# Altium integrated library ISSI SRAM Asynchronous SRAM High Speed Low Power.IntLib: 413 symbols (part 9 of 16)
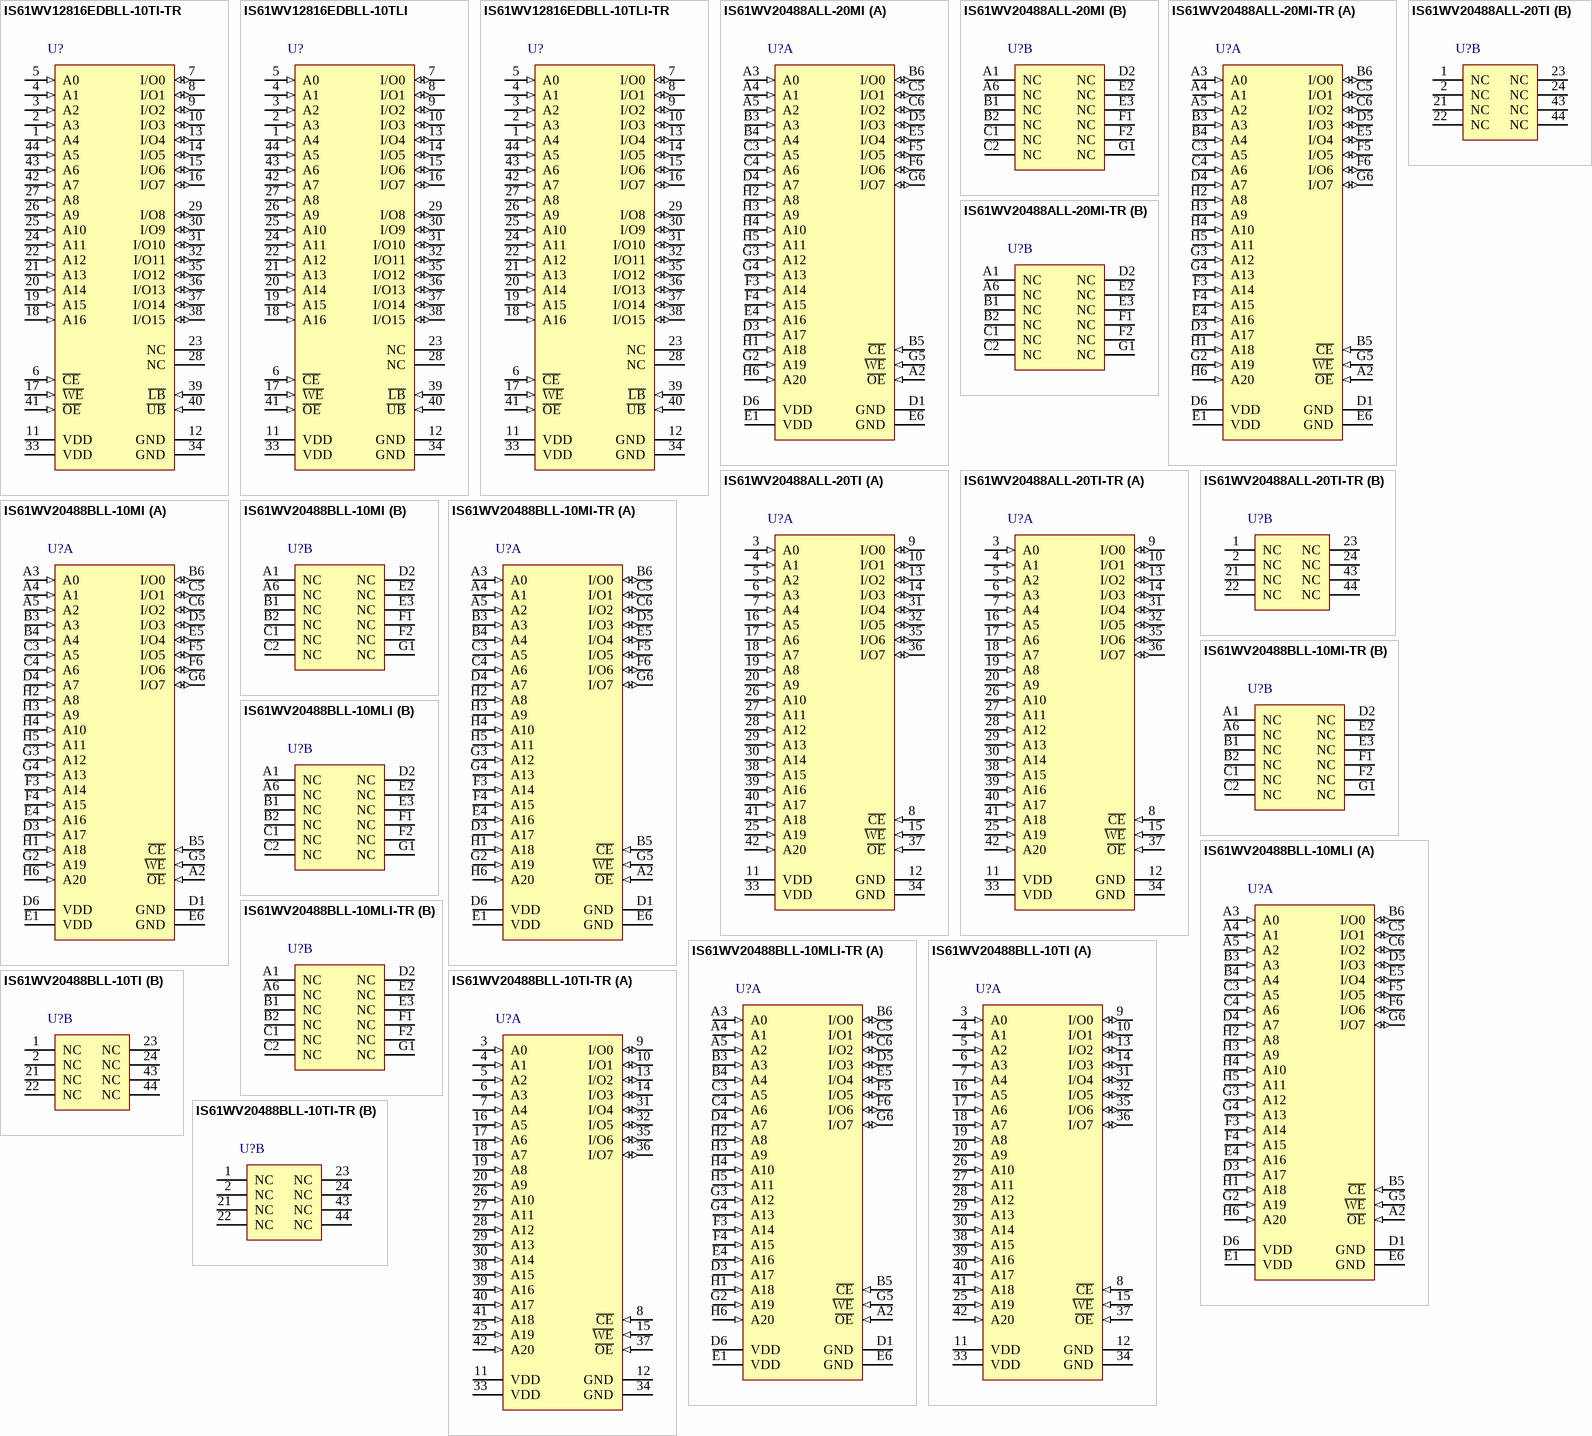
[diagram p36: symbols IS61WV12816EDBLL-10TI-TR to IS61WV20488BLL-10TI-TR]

## IS61WV20488BLL-10MI
designator U?
16 M High Speed CMOS SRAM, 2 M x 8, -40 to 85 degC, 48-Pin BGA (TF-BGA-48); Manufacturer: Integrated Silicon Solution Inc (ISSI); PartNumber: IS61WV20488BLL-10MI; Organization: 2M x 8; Packing: Tray / Tube; Speed (ns): 10
footprint ISSI-TF-BGA-48-9000x11000DE (BGA, 48-Balls, Body 11x9mm, Pitch 0.75mm)
part A pins: A2 ~{OE} (in) "Output Enable Input", A3 A0 (in) "Address Input", A4 A1 (in) "Address Input", A5 A2 (in) "Address Input", B3 A3 (in) "Address Input", B4 A4 (in) "Address Input", B5 ~{CE} (in) "Chip Enable Input", B6 I/O0 (io) "Data Input / Output", C3 A5 (in) "Address Input", C4 A6 (in) "Address Input", C5 I/O1 (io) "Data Input / Output", C6 I/O2 (io) "Data Input / Output", D1 GND (power) "Ground", D3 A17 (in) "Address Input", D4 A7 (in) "Address Input", D5 I/O3 (io) "Data Input / Output", D6 VDD (power) "Power", E1 VDD (power) "Power", E4 A16 (in) "Address Input", E5 I/O4 (io) "Data Input / Output", E6 GND (power) "Ground", F3 A14 (in) "Address Input", F4 A15 (in) "Address Input", F5 I/O5 (io) "Data Input / Output", F6 I/O6 (io) "Data Input / Output", G2 A19 (in) "Address Input", G3 A12 (in) "Address Input", G4 A13 (in) "Address Input", G5 ~{WE} (in) "Write Enable Input", G6 I/O7 (io) "Data Input / Output", H1 A18 (in) "Address Input", H2 A8 (in) "Address Input", H3 A9 (in) "Address Input", H4 A10 (in) "Address Input", H5 A11 (in) "Address Input", H6 A20 (in) "Address Input"
part B pins: A1 NC "No Connection", A6 NC "No Connection", B1 NC "No Connection", B2 NC "No Connection", C1 NC "No Connection", C2 NC "No Connection", D2 NC "No Connection", E2 NC "No Connection", E3 NC "No Connection", F1 NC "No Connection", F2 NC "No Connection", G1 NC "No Connection"

## IS61WV20488BLL-10MI-TR
designator U?
16 M High Speed CMOS SRAM, 2 M x 8, -40 to 85 degC, 48-Pin BGA (TF-BGA-48); Manufacturer: Integrated Silicon Solution Inc (ISSI); PartNumber: IS61WV20488BLL-10MI-TR; Organization: 2M x 8; Packing: Tape & Reel; Speed (ns): 10
footprint ISSI-TF-BGA-48-9000x11000DE (BGA, 48-Balls, Body 11x9mm, Pitch 0.75mm)
part A pins: A2 ~{OE} (in) "Output Enable Input", A3 A0 (in) "Address Input", A4 A1 (in) "Address Input", A5 A2 (in) "Address Input", B3 A3 (in) "Address Input", B4 A4 (in) "Address Input", B5 ~{CE} (in) "Chip Enable Input", B6 I/O0 (io) "Data Input / Output", C3 A5 (in) "Address Input", C4 A6 (in) "Address Input", C5 I/O1 (io) "Data Input / Output", C6 I/O2 (io) "Data Input / Output", D1 GND (power) "Ground", D3 A17 (in) "Address Input", D4 A7 (in) "Address Input", D5 I/O3 (io) "Data Input / Output", D6 VDD (power) "Power", E1 VDD (power) "Power", E4 A16 (in) "Address Input", E5 I/O4 (io) "Data Input / Output", E6 GND (power) "Ground", F3 A14 (in) "Address Input", F4 A15 (in) "Address Input", F5 I/O5 (io) "Data Input / Output", F6 I/O6 (io) "Data Input / Output", G2 A19 (in) "Address Input", G3 A12 (in) "Address Input", G4 A13 (in) "Address Input", G5 ~{WE} (in) "Write Enable Input", G6 I/O7 (io) "Data Input / Output", H1 A18 (in) "Address Input", H2 A8 (in) "Address Input", H3 A9 (in) "Address Input", H4 A10 (in) "Address Input", H5 A11 (in) "Address Input", H6 A20 (in) "Address Input"
part B pins: A1 NC "No Connection", A6 NC "No Connection", B1 NC "No Connection", B2 NC "No Connection", C1 NC "No Connection", C2 NC "No Connection", D2 NC "No Connection", E2 NC "No Connection", E3 NC "No Connection", F1 NC "No Connection", F2 NC "No Connection", G1 NC "No Connection"

## IS61WV20488BLL-10MLI
designator U?
16 M High Speed CMOS SRAM, 2 M x 8, -40 to 85 degC, 48-Pin BGA (TF-BGA-48), Pb-Free; Manufacturer: Integrated Silicon Solution Inc (ISSI); PartNumber: IS61WV20488BLL-10MLI; Organization: 2M x 8; Packing: Tray / Tube; Speed (ns): 10
footprint ISSI-TF-BGA-48-9000x11000DE (BGA, 48-Balls, Body 11x9mm, Pitch 0.75mm)
part A pins: A2 ~{OE} (in) "Output Enable Input", A3 A0 (in) "Address Input", A4 A1 (in) "Address Input", A5 A2 (in) "Address Input", B3 A3 (in) "Address Input", B4 A4 (in) "Address Input", B5 ~{CE} (in) "Chip Enable Input", B6 I/O0 (io) "Data Input / Output", C3 A5 (in) "Address Input", C4 A6 (in) "Address Input", C5 I/O1 (io) "Data Input / Output", C6 I/O2 (io) "Data Input / Output", D1 GND (power) "Ground", D3 A17 (in) "Address Input", D4 A7 (in) "Address Input", D5 I/O3 (io) "Data Input / Output", D6 VDD (power) "Power", E1 VDD (power) "Power", E4 A16 (in) "Address Input", E5 I/O4 (io) "Data Input / Output", E6 GND (power) "Ground", F3 A14 (in) "Address Input", F4 A15 (in) "Address Input", F5 I/O5 (io) "Data Input / Output", F6 I/O6 (io) "Data Input / Output", G2 A19 (in) "Address Input", G3 A12 (in) "Address Input", G4 A13 (in) "Address Input", G5 ~{WE} (in) "Write Enable Input", G6 I/O7 (io) "Data Input / Output", H1 A18 (in) "Address Input", H2 A8 (in) "Address Input", H3 A9 (in) "Address Input", H4 A10 (in) "Address Input", H5 A11 (in) "Address Input", H6 A20 (in) "Address Input"
part B pins: A1 NC "No Connection", A6 NC "No Connection", B1 NC "No Connection", B2 NC "No Connection", C1 NC "No Connection", C2 NC "No Connection", D2 NC "No Connection", E2 NC "No Connection", E3 NC "No Connection", F1 NC "No Connection", F2 NC "No Connection", G1 NC "No Connection"

## IS61WV20488BLL-10MLI-TR
designator U?
16 M High Speed CMOS SRAM, 2 M x 8, -40 to 85 degC, 48-Pin BGA (TF-BGA-48), Pb-Free; Manufacturer: Integrated Silicon Solution Inc (ISSI); PartNumber: IS61WV20488BLL-10MLI-TR; Organization: 2M x 8; Packing: Tape & Reel; Speed (ns): 10
footprint ISSI-TF-BGA-48-9000x11000DE (BGA, 48-Balls, Body 11x9mm, Pitch 0.75mm)
part A pins: A2 ~{OE} (in) "Output Enable Input", A3 A0 (in) "Address Input", A4 A1 (in) "Address Input", A5 A2 (in) "Address Input", B3 A3 (in) "Address Input", B4 A4 (in) "Address Input", B5 ~{CE} (in) "Chip Enable Input", B6 I/O0 (io) "Data Input / Output", C3 A5 (in) "Address Input", C4 A6 (in) "Address Input", C5 I/O1 (io) "Data Input / Output", C6 I/O2 (io) "Data Input / Output", D1 GND (power) "Ground", D3 A17 (in) "Address Input", D4 A7 (in) "Address Input", D5 I/O3 (io) "Data Input / Output", D6 VDD (power) "Power", E1 VDD (power) "Power", E4 A16 (in) "Address Input", E5 I/O4 (io) "Data Input / Output", E6 GND (power) "Ground", F3 A14 (in) "Address Input", F4 A15 (in) "Address Input", F5 I/O5 (io) "Data Input / Output", F6 I/O6 (io) "Data Input / Output", G2 A19 (in) "Address Input", G3 A12 (in) "Address Input", G4 A13 (in) "Address Input", G5 ~{WE} (in) "Write Enable Input", G6 I/O7 (io) "Data Input / Output", H1 A18 (in) "Address Input", H2 A8 (in) "Address Input", H3 A9 (in) "Address Input", H4 A10 (in) "Address Input", H5 A11 (in) "Address Input", H6 A20 (in) "Address Input"
part B pins: A1 NC "No Connection", A6 NC "No Connection", B1 NC "No Connection", B2 NC "No Connection", C1 NC "No Connection", C2 NC "No Connection", D2 NC "No Connection", E2 NC "No Connection", E3 NC "No Connection", F1 NC "No Connection", F2 NC "No Connection", G1 NC "No Connection"

## IS61WV20488BLL-10TI
designator U?
16 M High Speed CMOS SRAM, 2 M x 8, -40 to 85 degC, 44-Pin SOP (TSOP-2-44); Manufacturer: Integrated Silicon Solution Inc (ISSI); PartNumber: IS61WV20488BLL-10TI; Organization: 2M x 8; Packing: Tray / Tube; Speed (ns): 10
footprint ISSI-TSOP-2-44_N (SOP, 44-Leads, Body 18.5x10.3mm, Pitch 0.8mm, IPC Medium Density)
part A pins: 3 A0 (in) "Address Inputs", 4 A1 (in) "Address Inputs", 5 A2 (in) "Address Inputs", 6 A3 (in) "Address Inputs", 7 A4 (in) "Address Inputs", 8 ~{CE} (in) "Chip Enable Input", 9 I/O0 (io) "Data Input / Output", 10 I/O1 (io) "Data Input / Output", 11 VDD (power) "Power", 12 GND (power) "Ground", 13 I/O2 (io) "Data Input / Output", 14 I/O3 (io) "Data Input / Output", 15 ~{WE} (in) "Write Enable Input", 16 A5 (in) "Address Inputs", 17 A6 (in) "Address Inputs", 18 A7 (in) "Address Inputs", 19 A8 (in) "Address Inputs", 20 A9 (in) "Address Inputs", 25 A19 (in) "Address Inputs", 26 A10 (in) "Address Inputs", 27 A11 (in) "Address Inputs", 28 A12 (in) "Address Inputs", 29 A13 (in) "Address Inputs", 30 A14 (in) "Address Inputs", 31 I/O4 (io) "Data Input / Output", 32 I/O5 (io) "Data Input / Output", 33 VDD (power) "Power", 34 GND (power) "Ground", 35 I/O6 (io) "Data Input / Output", 36 I/O7 (io) "Data Input / Output", 37 ~{OE} (in) "Output Enable Input", 38 A15 (in) "Address Inputs", 39 A16 (in) "Address Inputs", 40 A17 (in) "Address Inputs", 41 A18 (in) "Address Inputs", 42 A20 (in) "Address Inputs"
part B pins: 1 NC "No Connection", 2 NC "No Connection", 21 NC "No Connection", 22 NC "No Connection", 23 NC "No Connection", 24 NC "No Connection", 43 NC "No Connection", 44 NC "No Connection"

## IS61WV20488BLL-10TI-TR
designator U?
16 M High Speed CMOS SRAM, 2 M x 8, -40 to 85 degC, 44-Pin SOP (TSOP-2-44); Manufacturer: Integrated Silicon Solution Inc (ISSI); PartNumber: IS61WV20488BLL-10TI-TR; Organization: 2M x 8; Packing: Tape & Reel; Speed (ns): 10
footprint ISSI-TSOP-2-44_N (SOP, 44-Leads, Body 18.5x10.3mm, Pitch 0.8mm, IPC Medium Density)
part A pins: 3 A0 (in) "Address Inputs", 4 A1 (in) "Address Inputs", 5 A2 (in) "Address Inputs", 6 A3 (in) "Address Inputs", 7 A4 (in) "Address Inputs", 8 ~{CE} (in) "Chip Enable Input", 9 I/O0 (io) "Data Input / Output", 10 I/O1 (io) "Data Input / Output", 11 VDD (power) "Power", 12 GND (power) "Ground", 13 I/O2 (io) "Data Input / Output", 14 I/O3 (io) "Data Input / Output", 15 ~{WE} (in) "Write Enable Input", 16 A5 (in) "Address Inputs", 17 A6 (in) "Address Inputs", 18 A7 (in) "Address Inputs", 19 A8 (in) "Address Inputs", 20 A9 (in) "Address Inputs", 25 A19 (in) "Address Inputs", 26 A10 (in) "Address Inputs", 27 A11 (in) "Address Inputs", 28 A12 (in) "Address Inputs", 29 A13 (in) "Address Inputs", 30 A14 (in) "Address Inputs", 31 I/O4 (io) "Data Input / Output", 32 I/O5 (io) "Data Input / Output", 33 VDD (power) "Power", 34 GND (power) "Ground", 35 I/O6 (io) "Data Input / Output", 36 I/O7 (io) "Data Input / Output", 37 ~{OE} (in) "Output Enable Input", 38 A15 (in) "Address Inputs", 39 A16 (in) "Address Inputs", 40 A17 (in) "Address Inputs", 41 A18 (in) "Address Inputs", 42 A20 (in) "Address Inputs"
part B pins: 1 NC "No Connection", 2 NC "No Connection", 21 NC "No Connection", 22 NC "No Connection", 23 NC "No Connection", 24 NC "No Connection", 43 NC "No Connection", 44 NC "No Connection"

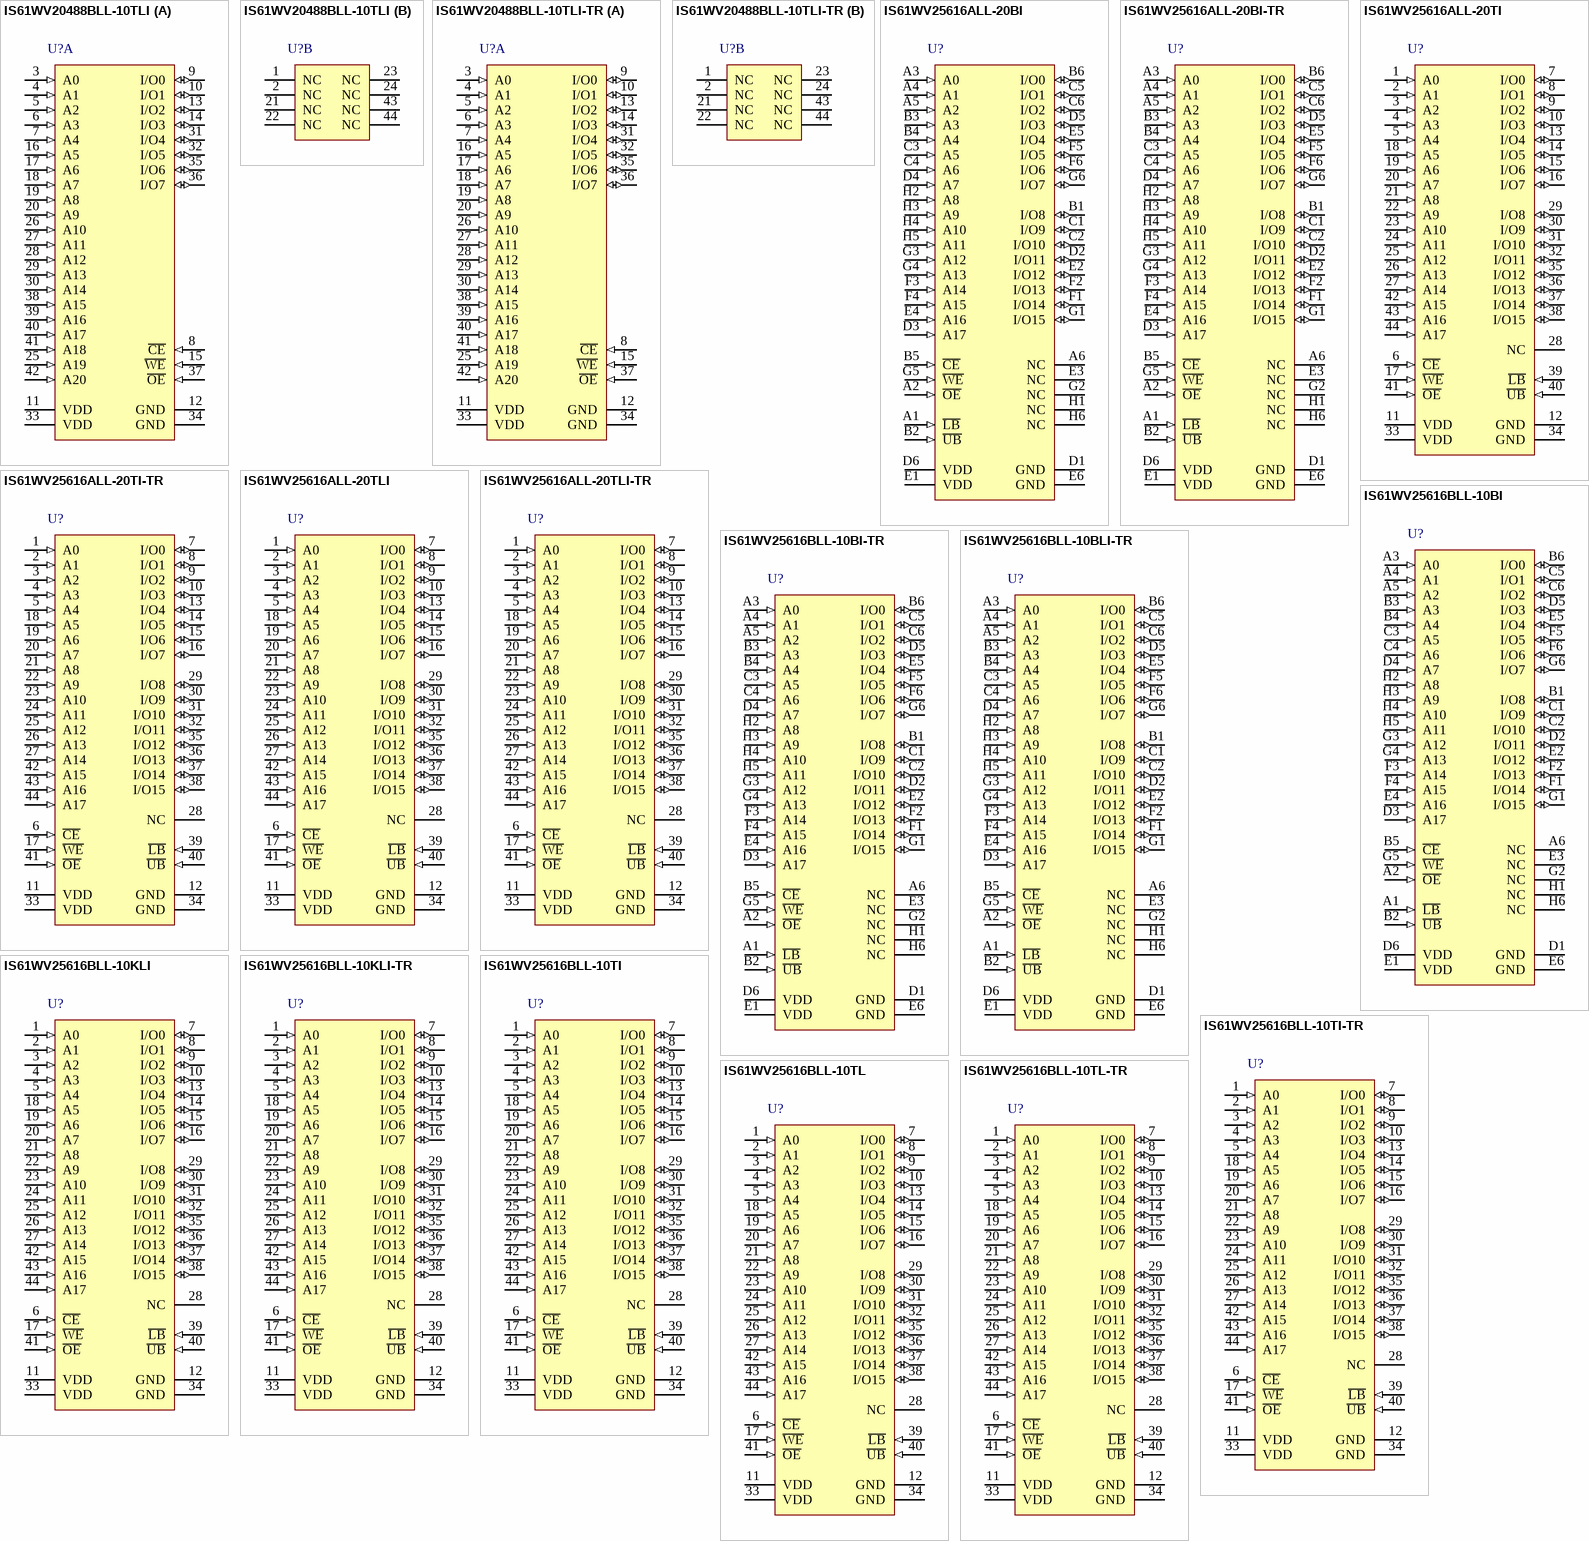
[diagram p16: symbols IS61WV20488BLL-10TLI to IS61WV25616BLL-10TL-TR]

## IS61WV20488BLL-10TLI
designator U?
16 M High Speed CMOS SRAM, 2 M x 8, -40 to 85 degC, 44-Pin SOP (TSOP-2-44), Pb-Free; Manufacturer: Integrated Silicon Solution Inc (ISSI); PartNumber: IS61WV20488BLL-10TLI; Organization: 2M x 8; Packing: Tray / Tube; Speed (ns): 10
footprint ISSI-TSOP-2-44_N (SOP, 44-Leads, Body 18.5x10.3mm, Pitch 0.8mm, IPC Medium Density)
part A pins: 3 A0 (in) "Address Inputs", 4 A1 (in) "Address Inputs", 5 A2 (in) "Address Inputs", 6 A3 (in) "Address Inputs", 7 A4 (in) "Address Inputs", 8 ~{CE} (in) "Chip Enable Input", 9 I/O0 (io) "Data Input / Output", 10 I/O1 (io) "Data Input / Output", 11 VDD (power) "Power", 12 GND (power) "Ground", 13 I/O2 (io) "Data Input / Output", 14 I/O3 (io) "Data Input / Output", 15 ~{WE} (in) "Write Enable Input", 16 A5 (in) "Address Inputs", 17 A6 (in) "Address Inputs", 18 A7 (in) "Address Inputs", 19 A8 (in) "Address Inputs", 20 A9 (in) "Address Inputs", 25 A19 (in) "Address Inputs", 26 A10 (in) "Address Inputs", 27 A11 (in) "Address Inputs", 28 A12 (in) "Address Inputs", 29 A13 (in) "Address Inputs", 30 A14 (in) "Address Inputs", 31 I/O4 (io) "Data Input / Output", 32 I/O5 (io) "Data Input / Output", 33 VDD (power) "Power", 34 GND (power) "Ground", 35 I/O6 (io) "Data Input / Output", 36 I/O7 (io) "Data Input / Output", 37 ~{OE} (in) "Output Enable Input", 38 A15 (in) "Address Inputs", 39 A16 (in) "Address Inputs", 40 A17 (in) "Address Inputs", 41 A18 (in) "Address Inputs", 42 A20 (in) "Address Inputs"
part B pins: 1 NC "No Connection", 2 NC "No Connection", 21 NC "No Connection", 22 NC "No Connection", 23 NC "No Connection", 24 NC "No Connection", 43 NC "No Connection", 44 NC "No Connection"

## IS61WV20488BLL-10TLI-TR
designator U?
16 M High Speed CMOS SRAM, 2 M x 8, -40 to 85 degC, 44-Pin SOP (TSOP-2-44), Pb-Free; Manufacturer: Integrated Silicon Solution Inc (ISSI); PartNumber: IS61WV20488BLL-10TLI-TR; Organization: 2M x 8; Packing: Tape & Reel; Speed (ns): 10
footprint ISSI-TSOP-2-44_N (SOP, 44-Leads, Body 18.5x10.3mm, Pitch 0.8mm, IPC Medium Density)
part A pins: 3 A0 (in) "Address Inputs", 4 A1 (in) "Address Inputs", 5 A2 (in) "Address Inputs", 6 A3 (in) "Address Inputs", 7 A4 (in) "Address Inputs", 8 ~{CE} (in) "Chip Enable Input", 9 I/O0 (io) "Data Input / Output", 10 I/O1 (io) "Data Input / Output", 11 VDD (power) "Power", 12 GND (power) "Ground", 13 I/O2 (io) "Data Input / Output", 14 I/O3 (io) "Data Input / Output", 15 ~{WE} (in) "Write Enable Input", 16 A5 (in) "Address Inputs", 17 A6 (in) "Address Inputs", 18 A7 (in) "Address Inputs", 19 A8 (in) "Address Inputs", 20 A9 (in) "Address Inputs", 25 A19 (in) "Address Inputs", 26 A10 (in) "Address Inputs", 27 A11 (in) "Address Inputs", 28 A12 (in) "Address Inputs", 29 A13 (in) "Address Inputs", 30 A14 (in) "Address Inputs", 31 I/O4 (io) "Data Input / Output", 32 I/O5 (io) "Data Input / Output", 33 VDD (power) "Power", 34 GND (power) "Ground", 35 I/O6 (io) "Data Input / Output", 36 I/O7 (io) "Data Input / Output", 37 ~{OE} (in) "Output Enable Input", 38 A15 (in) "Address Inputs", 39 A16 (in) "Address Inputs", 40 A17 (in) "Address Inputs", 41 A18 (in) "Address Inputs", 42 A20 (in) "Address Inputs"
part B pins: 1 NC "No Connection", 2 NC "No Connection", 21 NC "No Connection", 22 NC "No Connection", 23 NC "No Connection", 24 NC "No Connection", 43 NC "No Connection", 44 NC "No Connection"

## IS61WV25616ALL-20BI
designator U?
4 M High Speed Asynchronous CMOS SRAM, 256 K x 16, -40 to 85 degC, 48-Pin BGA (TF-BGA-48); Manufacturer: Integrated Silicon Solution Inc (ISSI); PartNumber: IS61WV25616ALL-20BI; Packing: Tray / Tube; Speed (ns): 20
footprint ISSI-TF-BGA-48-6000X8000DE (BGA, 48-Balls, Body 8x6mm, Pitch 0.75mm)
pins: A1 ~{LB} (in) "Lower-byte Control (I/O0-I/O7)", A2 ~{OE} (in) "Output Enable Input", A3 A0 (in) "Address Input", A4 A1 (in) "Address Input", A5 A2 (in) "Address Input", A6 NC "No Connection", B1 I/O8 (io) "Data Input/Output", B2 ~{UB} (in) "Upper-byte Control (I/O8-I/O15)", B3 A3 (in) "Address Input", B4 A4 (in) "Address Input", B5 ~{CE} (in) "Chip Enable Input", B6 I/O0 (io) "Data Input/Output", C1 I/O9 (io) "Data Input/Output", C2 I/O10 (io) "Data Input/Output", C3 A5 (in) "Address Input", C4 A6 (in) "Address Input", C5 I/O1 (io) "Data Input/Output", C6 I/O2 (io) "Data Input/Output", D1 GND (power) "Ground", D2 I/O11 (io) "Data Input/Output", D3 A17 (in) "Address Input", D4 A7 (in) "Address Input", D5 I/O3 (io) "Data Input/Output", D6 VDD (power) "Power", E1 VDD (power) "Power", E2 I/O12 (io) "Data Input/Output", E3 NC "No Connection", E4 A16 (in) "Address Input", E5 I/O4 (io) "Data Input/Output", E6 GND (power) "Ground", F1 I/O14 (io) "Data Input/Output", F2 I/O13 (io) "Data Input/Output", F3 A14 (in) "Address Input", F4 A15 (in) "Address Input", F5 I/O5 (io) "Data Input/Output", F6 I/O6 (io) "Data Input/Output", G1 I/O15 (io) "Data Input/Output", G2 NC "No Connection", G3 A12 (in) "Address Input", G4 A13 (in) "Address Input", G5 ~{WE} (in) "Write Enable Input", G6 I/O7 (io) "Data Input/Output", H1 NC "No Connection", H2 A8 (in) "Address Input", H3 A9 (in) "Address Input", H4 A10 (in) "Address Input", H5 A11 (in) "Address Input", H6 NC "No Connection"

## IS61WV25616ALL-20BI-TR
designator U?
4 M High Speed Asynchronous CMOS SRAM, 256 K x 16, -40 to 85 degC, 48-Pin BGA (TF-BGA-48); Manufacturer: Integrated Silicon Solution Inc (ISSI); PartNumber: IS61WV25616ALL-20BI-TR; Packing: Tape & Reel; Speed (ns): 20
footprint ISSI-TF-BGA-48-6000X8000DE (BGA, 48-Balls, Body 8x6mm, Pitch 0.75mm)
pins: A1 ~{LB} (in) "Lower-byte Control (I/O0-I/O7)", A2 ~{OE} (in) "Output Enable Input", A3 A0 (in) "Address Input", A4 A1 (in) "Address Input", A5 A2 (in) "Address Input", A6 NC "No Connection", B1 I/O8 (io) "Data Input/Output", B2 ~{UB} (in) "Upper-byte Control (I/O8-I/O15)", B3 A3 (in) "Address Input", B4 A4 (in) "Address Input", B5 ~{CE} (in) "Chip Enable Input", B6 I/O0 (io) "Data Input/Output", C1 I/O9 (io) "Data Input/Output", C2 I/O10 (io) "Data Input/Output", C3 A5 (in) "Address Input", C4 A6 (in) "Address Input", C5 I/O1 (io) "Data Input/Output", C6 I/O2 (io) "Data Input/Output", D1 GND (power) "Ground", D2 I/O11 (io) "Data Input/Output", D3 A17 (in) "Address Input", D4 A7 (in) "Address Input", D5 I/O3 (io) "Data Input/Output", D6 VDD (power) "Power", E1 VDD (power) "Power", E2 I/O12 (io) "Data Input/Output", E3 NC "No Connection", E4 A16 (in) "Address Input", E5 I/O4 (io) "Data Input/Output", E6 GND (power) "Ground", F1 I/O14 (io) "Data Input/Output", F2 I/O13 (io) "Data Input/Output", F3 A14 (in) "Address Input", F4 A15 (in) "Address Input", F5 I/O5 (io) "Data Input/Output", F6 I/O6 (io) "Data Input/Output", G1 I/O15 (io) "Data Input/Output", G2 NC "No Connection", G3 A12 (in) "Address Input", G4 A13 (in) "Address Input", G5 ~{WE} (in) "Write Enable Input", G6 I/O7 (io) "Data Input/Output", H1 NC "No Connection", H2 A8 (in) "Address Input", H3 A9 (in) "Address Input", H4 A10 (in) "Address Input", H5 A11 (in) "Address Input", H6 NC "No Connection"

## IS61WV25616ALL-20TI
designator U?
4 M High Speed Asynchronous CMOS SRAM, 256 K x 16, -40 to 85 degC, 44-Pin SOP (TSOP-2-44); Manufacturer: Integrated Silicon Solution Inc (ISSI); PartNumber: IS61WV25616ALL-20TI; Packing: Tray / Tube; Speed (ns): 20
footprint ISSI-TSOP-2-44_N (SOP, 44-Leads, Body 18.5x10.3mm, Pitch 0.8mm, IPC Medium Density)
pins: 1 A0 (in) "Address Input", 2 A1 (in) "Address Input", 3 A2 (in) "Address Input", 4 A3 (in) "Address Input", 5 A4 (in) "Address Input", 6 ~{CE} (in) "Chip Enable Input", 7 I/O0 (io) "Data Input/Output", 8 I/O1 (io) "Data Input/Output", 9 I/O2 (io) "Data Input/Output", 10 I/O3 (io) "Data Input/Output", 11 VDD (power) "Power", 12 GND (power) "Ground", 13 I/O4 (io) "Data Input/Output", 14 I/O5 (io) "Data Input/Output", 15 I/O6 (io) "Data Input/Output", 16 I/O7 (io) "Data Input/Output", 17 ~{WE} (in) "Write Enable Input", 18 A5 (in) "Address Input", 19 A6 (in) "Address Input", 20 A7 (in) "Address Input", 21 A8 (in) "Address Input", 22 A9 (in) "Address Input", 23 A10 (in) "Address Input", 24 A11 (in) "Address Input", 25 A12 (in) "Address Input", 26 A13 (in) "Address Input", 27 A14 (in) "Address Input", 28 NC "No Connection", 29 I/O8 (io) "Data Input/Output", 30 I/O9 (io) "Data Input/Output", 31 I/O10 (io) "Data Input/Output", 32 I/O11 (io) "Data Input/Output", 33 VDD (power) "Power", 34 GND (power) "Ground", 35 I/O12 (io) "Data Input/Output", 36 I/O13 (io) "Data Input/Output", 37 I/O14 (io) "Data Input/Output", 38 I/O15 (io) "Data Input/Output", 39 ~{LB} (in) "Lower-byte Control (I/O0-I/O7)", 40 ~{UB} (in) "Upper-byte Control (I/O8-I/O15)", 41 ~{OE} (in) "Output Enable Input", 42 A15 (in) "Address Input", 43 A16 (in) "Address Input", 44 A17 (in) "Address Input"

## IS61WV25616ALL-20TI-TR
designator U?
4 M High Speed Asynchronous CMOS SRAM, 256 K x 16, -40 to 85 degC, 44-Pin SOP (TSOP-2-44); Manufacturer: Integrated Silicon Solution Inc (ISSI); PartNumber: IS61WV25616ALL-20TI-TR; Packing: Tape & Reel; Speed (ns): 20
footprint ISSI-TSOP-2-44_N (SOP, 44-Leads, Body 18.5x10.3mm, Pitch 0.8mm, IPC Medium Density)
pins: 1 A0 (in) "Address Input", 2 A1 (in) "Address Input", 3 A2 (in) "Address Input", 4 A3 (in) "Address Input", 5 A4 (in) "Address Input", 6 ~{CE} (in) "Chip Enable Input", 7 I/O0 (io) "Data Input/Output", 8 I/O1 (io) "Data Input/Output", 9 I/O2 (io) "Data Input/Output", 10 I/O3 (io) "Data Input/Output", 11 VDD (power) "Power", 12 GND (power) "Ground", 13 I/O4 (io) "Data Input/Output", 14 I/O5 (io) "Data Input/Output", 15 I/O6 (io) "Data Input/Output", 16 I/O7 (io) "Data Input/Output", 17 ~{WE} (in) "Write Enable Input", 18 A5 (in) "Address Input", 19 A6 (in) "Address Input", 20 A7 (in) "Address Input", 21 A8 (in) "Address Input", 22 A9 (in) "Address Input", 23 A10 (in) "Address Input", 24 A11 (in) "Address Input", 25 A12 (in) "Address Input", 26 A13 (in) "Address Input", 27 A14 (in) "Address Input", 28 NC "No Connection", 29 I/O8 (io) "Data Input/Output", 30 I/O9 (io) "Data Input/Output", 31 I/O10 (io) "Data Input/Output", 32 I/O11 (io) "Data Input/Output", 33 VDD (power) "Power", 34 GND (power) "Ground", 35 I/O12 (io) "Data Input/Output", 36 I/O13 (io) "Data Input/Output", 37 I/O14 (io) "Data Input/Output", 38 I/O15 (io) "Data Input/Output", 39 ~{LB} (in) "Lower-byte Control (I/O0-I/O7)", 40 ~{UB} (in) "Upper-byte Control (I/O8-I/O15)", 41 ~{OE} (in) "Output Enable Input", 42 A15 (in) "Address Input", 43 A16 (in) "Address Input", 44 A17 (in) "Address Input"

## IS61WV25616ALL-20TLI
designator U?
4 M High Speed Asynchronous CMOS SRAM, 256 K x 16, -40 to 85 degC, 44-Pin SOP (TSOP-2-44), Pb-Free; Manufacturer: Integrated Silicon Solution Inc (ISSI); PartNumber: IS61WV25616ALL-20TLI; Packing: Tray / Tube; Speed (ns): 20
footprint ISSI-TSOP-2-44_N (SOP, 44-Leads, Body 18.5x10.3mm, Pitch 0.8mm, IPC Medium Density)
pins: 1 A0 (in) "Address Input", 2 A1 (in) "Address Input", 3 A2 (in) "Address Input", 4 A3 (in) "Address Input", 5 A4 (in) "Address Input", 6 ~{CE} (in) "Chip Enable Input", 7 I/O0 (io) "Data Input/Output", 8 I/O1 (io) "Data Input/Output", 9 I/O2 (io) "Data Input/Output", 10 I/O3 (io) "Data Input/Output", 11 VDD (power) "Power", 12 GND (power) "Ground", 13 I/O4 (io) "Data Input/Output", 14 I/O5 (io) "Data Input/Output", 15 I/O6 (io) "Data Input/Output", 16 I/O7 (io) "Data Input/Output", 17 ~{WE} (in) "Write Enable Input", 18 A5 (in) "Address Input", 19 A6 (in) "Address Input", 20 A7 (in) "Address Input", 21 A8 (in) "Address Input", 22 A9 (in) "Address Input", 23 A10 (in) "Address Input", 24 A11 (in) "Address Input", 25 A12 (in) "Address Input", 26 A13 (in) "Address Input", 27 A14 (in) "Address Input", 28 NC "No Connection", 29 I/O8 (io) "Data Input/Output", 30 I/O9 (io) "Data Input/Output", 31 I/O10 (io) "Data Input/Output", 32 I/O11 (io) "Data Input/Output", 33 VDD (power) "Power", 34 GND (power) "Ground", 35 I/O12 (io) "Data Input/Output", 36 I/O13 (io) "Data Input/Output", 37 I/O14 (io) "Data Input/Output", 38 I/O15 (io) "Data Input/Output", 39 ~{LB} (in) "Lower-byte Control (I/O0-I/O7)", 40 ~{UB} (in) "Upper-byte Control (I/O8-I/O15)", 41 ~{OE} (in) "Output Enable Input", 42 A15 (in) "Address Input", 43 A16 (in) "Address Input", 44 A17 (in) "Address Input"

## IS61WV25616ALL-20TLI-TR
designator U?
4 M High Speed Asynchronous CMOS SRAM, 256 K x 16, -40 to 85 degC, 44-Pin SOP (TSOP-2-44), Pb-Free; Manufacturer: Integrated Silicon Solution Inc (ISSI); PartNumber: IS61WV25616ALL-20TLI-TR; Packing: Tape & Reel; Speed (ns): 20
footprint ISSI-TSOP-2-44_N (SOP, 44-Leads, Body 18.5x10.3mm, Pitch 0.8mm, IPC Medium Density)
pins: 1 A0 (in) "Address Input", 2 A1 (in) "Address Input", 3 A2 (in) "Address Input", 4 A3 (in) "Address Input", 5 A4 (in) "Address Input", 6 ~{CE} (in) "Chip Enable Input", 7 I/O0 (io) "Data Input/Output", 8 I/O1 (io) "Data Input/Output", 9 I/O2 (io) "Data Input/Output", 10 I/O3 (io) "Data Input/Output", 11 VDD (power) "Power", 12 GND (power) "Ground", 13 I/O4 (io) "Data Input/Output", 14 I/O5 (io) "Data Input/Output", 15 I/O6 (io) "Data Input/Output", 16 I/O7 (io) "Data Input/Output", 17 ~{WE} (in) "Write Enable Input", 18 A5 (in) "Address Input", 19 A6 (in) "Address Input", 20 A7 (in) "Address Input", 21 A8 (in) "Address Input", 22 A9 (in) "Address Input", 23 A10 (in) "Address Input", 24 A11 (in) "Address Input", 25 A12 (in) "Address Input", 26 A13 (in) "Address Input", 27 A14 (in) "Address Input", 28 NC "No Connection", 29 I/O8 (io) "Data Input/Output", 30 I/O9 (io) "Data Input/Output", 31 I/O10 (io) "Data Input/Output", 32 I/O11 (io) "Data Input/Output", 33 VDD (power) "Power", 34 GND (power) "Ground", 35 I/O12 (io) "Data Input/Output", 36 I/O13 (io) "Data Input/Output", 37 I/O14 (io) "Data Input/Output", 38 I/O15 (io) "Data Input/Output", 39 ~{LB} (in) "Lower-byte Control (I/O0-I/O7)", 40 ~{UB} (in) "Upper-byte Control (I/O8-I/O15)", 41 ~{OE} (in) "Output Enable Input", 42 A15 (in) "Address Input", 43 A16 (in) "Address Input", 44 A17 (in) "Address Input"

## IS61WV25616BLL-10BI
designator U?
4 M High Speed Asynchronous CMOS SRAM, 256 K x 16, -40 to 85 degC, 48-Pin BGA (TF-BGA-48); Manufacturer: Integrated Silicon Solution Inc (ISSI); PartNumber: IS61WV25616BLL-10BI; Packing: Tray / Tube; Speed (ns): 10
footprint ISSI-TF-BGA-48-6000X8000DE (BGA, 48-Balls, Body 8x6mm, Pitch 0.75mm)
pins: A1 ~{LB} (in) "Lower-byte Control (I/O0-I/O7)", A2 ~{OE} (in) "Output Enable Input", A3 A0 (in) "Address Input", A4 A1 (in) "Address Input", A5 A2 (in) "Address Input", A6 NC "No Connection", B1 I/O8 (io) "Data Input/Output", B2 ~{UB} (in) "Upper-byte Control (I/O8-I/O15)", B3 A3 (in) "Address Input", B4 A4 (in) "Address Input", B5 ~{CE} (in) "Chip Enable Input", B6 I/O0 (io) "Data Input/Output", C1 I/O9 (io) "Data Input/Output", C2 I/O10 (io) "Data Input/Output", C3 A5 (in) "Address Input", C4 A6 (in) "Address Input", C5 I/O1 (io) "Data Input/Output", C6 I/O2 (io) "Data Input/Output", D1 GND (power) "Ground", D2 I/O11 (io) "Data Input/Output", D3 A17 (in) "Address Input", D4 A7 (in) "Address Input", D5 I/O3 (io) "Data Input/Output", D6 VDD (power) "Power", E1 VDD (power) "Power", E2 I/O12 (io) "Data Input/Output", E3 NC "No Connection", E4 A16 (in) "Address Input", E5 I/O4 (io) "Data Input/Output", E6 GND (power) "Ground", F1 I/O14 (io) "Data Input/Output", F2 I/O13 (io) "Data Input/Output", F3 A14 (in) "Address Input", F4 A15 (in) "Address Input", F5 I/O5 (io) "Data Input/Output", F6 I/O6 (io) "Data Input/Output", G1 I/O15 (io) "Data Input/Output", G2 NC "No Connection", G3 A12 (in) "Address Input", G4 A13 (in) "Address Input", G5 ~{WE} (in) "Write Enable Input", G6 I/O7 (io) "Data Input/Output", H1 NC "No Connection", H2 A8 (in) "Address Input", H3 A9 (in) "Address Input", H4 A10 (in) "Address Input", H5 A11 (in) "Address Input", H6 NC "No Connection"

## IS61WV25616BLL-10BI-TR
designator U?
4 M High Speed Asynchronous CMOS SRAM, 256 K x 16, -40 to 85 degC, 48-Pin BGA (TF-BGA-48); Manufacturer: Integrated Silicon Solution Inc (ISSI); PartNumber: IS61WV25616BLL-10BI-TR; Packing: Tape & Reel; Speed (ns): 10
footprint ISSI-TF-BGA-48-6000X8000DE (BGA, 48-Balls, Body 8x6mm, Pitch 0.75mm)
pins: A1 ~{LB} (in) "Lower-byte Control (I/O0-I/O7)", A2 ~{OE} (in) "Output Enable Input", A3 A0 (in) "Address Input", A4 A1 (in) "Address Input", A5 A2 (in) "Address Input", A6 NC "No Connection", B1 I/O8 (io) "Data Input/Output", B2 ~{UB} (in) "Upper-byte Control (I/O8-I/O15)", B3 A3 (in) "Address Input", B4 A4 (in) "Address Input", B5 ~{CE} (in) "Chip Enable Input", B6 I/O0 (io) "Data Input/Output", C1 I/O9 (io) "Data Input/Output", C2 I/O10 (io) "Data Input/Output", C3 A5 (in) "Address Input", C4 A6 (in) "Address Input", C5 I/O1 (io) "Data Input/Output", C6 I/O2 (io) "Data Input/Output", D1 GND (power) "Ground", D2 I/O11 (io) "Data Input/Output", D3 A17 (in) "Address Input", D4 A7 (in) "Address Input", D5 I/O3 (io) "Data Input/Output", D6 VDD (power) "Power", E1 VDD (power) "Power", E2 I/O12 (io) "Data Input/Output", E3 NC "No Connection", E4 A16 (in) "Address Input", E5 I/O4 (io) "Data Input/Output", E6 GND (power) "Ground", F1 I/O14 (io) "Data Input/Output", F2 I/O13 (io) "Data Input/Output", F3 A14 (in) "Address Input", F4 A15 (in) "Address Input", F5 I/O5 (io) "Data Input/Output", F6 I/O6 (io) "Data Input/Output", G1 I/O15 (io) "Data Input/Output", G2 NC "No Connection", G3 A12 (in) "Address Input", G4 A13 (in) "Address Input", G5 ~{WE} (in) "Write Enable Input", G6 I/O7 (io) "Data Input/Output", H1 NC "No Connection", H2 A8 (in) "Address Input", H3 A9 (in) "Address Input", H4 A10 (in) "Address Input", H5 A11 (in) "Address Input", H6 NC "No Connection"

## IS61WV25616BLL-10BLI-TR
designator U?
4 M High Speed Asynchronous CMOS SRAM, 256 K x 16, -40 to 85 degC, 48-Pin BGA (TF-BGA-48), Pb-Free; Manufacturer: Integrated Silicon Solution Inc (ISSI); PartNumber: IS61WV25616BLL-10BLI-TR; Packing: Tape & Reel; Speed (ns): 10
footprint ISSI-TF-BGA-48-6000X8000DE (BGA, 48-Balls, Body 8x6mm, Pitch 0.75mm)
pins: A1 ~{LB} (in) "Lower-byte Control (I/O0-I/O7)", A2 ~{OE} (in) "Output Enable Input", A3 A0 (in) "Address Input", A4 A1 (in) "Address Input", A5 A2 (in) "Address Input", A6 NC "No Connection", B1 I/O8 (io) "Data Input/Output", B2 ~{UB} (in) "Upper-byte Control (I/O8-I/O15)", B3 A3 (in) "Address Input", B4 A4 (in) "Address Input", B5 ~{CE} (in) "Chip Enable Input", B6 I/O0 (io) "Data Input/Output", C1 I/O9 (io) "Data Input/Output", C2 I/O10 (io) "Data Input/Output", C3 A5 (in) "Address Input", C4 A6 (in) "Address Input", C5 I/O1 (io) "Data Input/Output", C6 I/O2 (io) "Data Input/Output", D1 GND (power) "Ground", D2 I/O11 (io) "Data Input/Output", D3 A17 (in) "Address Input", D4 A7 (in) "Address Input", D5 I/O3 (io) "Data Input/Output", D6 VDD (power) "Power", E1 VDD (power) "Power", E2 I/O12 (io) "Data Input/Output", E3 NC "No Connection", E4 A16 (in) "Address Input", E5 I/O4 (io) "Data Input/Output", E6 GND (power) "Ground", F1 I/O14 (io) "Data Input/Output", F2 I/O13 (io) "Data Input/Output", F3 A14 (in) "Address Input", F4 A15 (in) "Address Input", F5 I/O5 (io) "Data Input/Output", F6 I/O6 (io) "Data Input/Output", G1 I/O15 (io) "Data Input/Output", G2 NC "No Connection", G3 A12 (in) "Address Input", G4 A13 (in) "Address Input", G5 ~{WE} (in) "Write Enable Input", G6 I/O7 (io) "Data Input/Output", H1 NC "No Connection", H2 A8 (in) "Address Input", H3 A9 (in) "Address Input", H4 A10 (in) "Address Input", H5 A11 (in) "Address Input", H6 NC "No Connection"

## IS61WV25616BLL-10KLI
designator U?
4 M High Speed Asynchronous CMOS SRAM, 256 K x 16, -40 to 85 degC, 44-Pin SOJ (SOJ-44), Pb-Free; Manufacturer: Integrated Silicon Solution Inc (ISSI); PartNumber: IS61WV25616BLL-10KLI; Packing: Tray / Tube; Speed (ns): 10
footprint ISSI-SOJ-44_N (SOJ, 44-Leads, Body 28.7x10.29mm, Pitch 1.27mm, IPC Medium Density)
pins: 1 A0 (in) "Address Input", 2 A1 (in) "Address Input", 3 A2 (in) "Address Input", 4 A3 (in) "Address Input", 5 A4 (in) "Address Input", 6 ~{CE} (in) "Chip Enable Input", 7 I/O0 (io) "Data Input/Output", 8 I/O1 (io) "Data Input/Output", 9 I/O2 (io) "Data Input/Output", 10 I/O3 (io) "Data Input/Output", 11 VDD (power) "Power", 12 GND (power) "Ground", 13 I/O4 (io) "Data Input/Output", 14 I/O5 (io) "Data Input/Output", 15 I/O6 (io) "Data Input/Output", 16 I/O7 (io) "Data Input/Output", 17 ~{WE} (in) "Write Enable Input", 18 A5 (in) "Address Input", 19 A6 (in) "Address Input", 20 A7 (in) "Address Input", 21 A8 (in) "Address Input", 22 A9 (in) "Address Input", 23 A10 (in) "Address Input", 24 A11 (in) "Address Input", 25 A12 (in) "Address Input", 26 A13 (in) "Address Input", 27 A14 (in) "Address Input", 28 NC "No Connection", 29 I/O8 (io) "Data Input/Output", 30 I/O9 (io) "Data Input/Output", 31 I/O10 (io) "Data Input/Output", 32 I/O11 (io) "Data Input/Output", 33 VDD (power) "Power", 34 GND (power) "Ground", 35 I/O12 (io) "Data Input/Output", 36 I/O13 (io) "Data Input/Output", 37 I/O14 (io) "Data Input/Output", 38 I/O15 (io) "Data Input/Output", 39 ~{LB} (in) "Lower-byte Control (I/O0-I/O7)", 40 ~{UB} (in) "Upper-byte Control (I/O8-I/O15)", 41 ~{OE} (in) "Output Enable Input", 42 A15 (in) "Address Input", 43 A16 (in) "Address Input", 44 A17 (in) "Address Input"

## IS61WV25616BLL-10KLI-TR
designator U?
4 M High Speed Asynchronous CMOS SRAM, 256 K x 16, -40 to 85 degC, 44-Pin SOJ (SOJ-44), Pb-Free; Manufacturer: Integrated Silicon Solution Inc (ISSI); PartNumber: IS61WV25616BLL-10KLI-TR; Packing: Tape & Reel; Speed (ns): 10
footprint ISSI-SOJ-44_N (SOJ, 44-Leads, Body 28.7x10.29mm, Pitch 1.27mm, IPC Medium Density)
pins: 1 A0 (in) "Address Input", 2 A1 (in) "Address Input", 3 A2 (in) "Address Input", 4 A3 (in) "Address Input", 5 A4 (in) "Address Input", 6 ~{CE} (in) "Chip Enable Input", 7 I/O0 (io) "Data Input/Output", 8 I/O1 (io) "Data Input/Output", 9 I/O2 (io) "Data Input/Output", 10 I/O3 (io) "Data Input/Output", 11 VDD (power) "Power", 12 GND (power) "Ground", 13 I/O4 (io) "Data Input/Output", 14 I/O5 (io) "Data Input/Output", 15 I/O6 (io) "Data Input/Output", 16 I/O7 (io) "Data Input/Output", 17 ~{WE} (in) "Write Enable Input", 18 A5 (in) "Address Input", 19 A6 (in) "Address Input", 20 A7 (in) "Address Input", 21 A8 (in) "Address Input", 22 A9 (in) "Address Input", 23 A10 (in) "Address Input", 24 A11 (in) "Address Input", 25 A12 (in) "Address Input", 26 A13 (in) "Address Input", 27 A14 (in) "Address Input", 28 NC "No Connection", 29 I/O8 (io) "Data Input/Output", 30 I/O9 (io) "Data Input/Output", 31 I/O10 (io) "Data Input/Output", 32 I/O11 (io) "Data Input/Output", 33 VDD (power) "Power", 34 GND (power) "Ground", 35 I/O12 (io) "Data Input/Output", 36 I/O13 (io) "Data Input/Output", 37 I/O14 (io) "Data Input/Output", 38 I/O15 (io) "Data Input/Output", 39 ~{LB} (in) "Lower-byte Control (I/O0-I/O7)", 40 ~{UB} (in) "Upper-byte Control (I/O8-I/O15)", 41 ~{OE} (in) "Output Enable Input", 42 A15 (in) "Address Input", 43 A16 (in) "Address Input", 44 A17 (in) "Address Input"

## IS61WV25616BLL-10TI
designator U?
4 M High Speed Asynchronous CMOS SRAM, 256 K x 16, -40 to 85 degC, 44-Pin SOP (TSOP-2-44); Manufacturer: Integrated Silicon Solution Inc (ISSI); PartNumber: IS61WV25616BLL-10TI; Packing: Tray / Tube; Speed (ns): 10
footprint ISSI-TSOP-2-44_N (SOP, 44-Leads, Body 18.5x10.3mm, Pitch 0.8mm, IPC Medium Density)
pins: 1 A0 (in) "Address Input", 2 A1 (in) "Address Input", 3 A2 (in) "Address Input", 4 A3 (in) "Address Input", 5 A4 (in) "Address Input", 6 ~{CE} (in) "Chip Enable Input", 7 I/O0 (io) "Data Input/Output", 8 I/O1 (io) "Data Input/Output", 9 I/O2 (io) "Data Input/Output", 10 I/O3 (io) "Data Input/Output", 11 VDD (power) "Power", 12 GND (power) "Ground", 13 I/O4 (io) "Data Input/Output", 14 I/O5 (io) "Data Input/Output", 15 I/O6 (io) "Data Input/Output", 16 I/O7 (io) "Data Input/Output", 17 ~{WE} (in) "Write Enable Input", 18 A5 (in) "Address Input", 19 A6 (in) "Address Input", 20 A7 (in) "Address Input", 21 A8 (in) "Address Input", 22 A9 (in) "Address Input", 23 A10 (in) "Address Input", 24 A11 (in) "Address Input", 25 A12 (in) "Address Input", 26 A13 (in) "Address Input", 27 A14 (in) "Address Input", 28 NC "No Connection", 29 I/O8 (io) "Data Input/Output", 30 I/O9 (io) "Data Input/Output", 31 I/O10 (io) "Data Input/Output", 32 I/O11 (io) "Data Input/Output", 33 VDD (power) "Power", 34 GND (power) "Ground", 35 I/O12 (io) "Data Input/Output", 36 I/O13 (io) "Data Input/Output", 37 I/O14 (io) "Data Input/Output", 38 I/O15 (io) "Data Input/Output", 39 ~{LB} (in) "Lower-byte Control (I/O0-I/O7)", 40 ~{UB} (in) "Upper-byte Control (I/O8-I/O15)", 41 ~{OE} (in) "Output Enable Input", 42 A15 (in) "Address Input", 43 A16 (in) "Address Input", 44 A17 (in) "Address Input"

## IS61WV25616BLL-10TI-TR
designator U?
4 M High Speed Asynchronous CMOS SRAM, 256 K x 16, -40 to 85 degC, 44-Pin SOP (TSOP-2-44); Manufacturer: Integrated Silicon Solution Inc (ISSI); PartNumber: IS61WV25616BLL-10TI-TR; Packing: Tape & Reel; Speed (ns): 10
footprint ISSI-TSOP-2-44_N (SOP, 44-Leads, Body 18.5x10.3mm, Pitch 0.8mm, IPC Medium Density)
pins: 1 A0 (in) "Address Input", 2 A1 (in) "Address Input", 3 A2 (in) "Address Input", 4 A3 (in) "Address Input", 5 A4 (in) "Address Input", 6 ~{CE} (in) "Chip Enable Input", 7 I/O0 (io) "Data Input/Output", 8 I/O1 (io) "Data Input/Output", 9 I/O2 (io) "Data Input/Output", 10 I/O3 (io) "Data Input/Output", 11 VDD (power) "Power", 12 GND (power) "Ground", 13 I/O4 (io) "Data Input/Output", 14 I/O5 (io) "Data Input/Output", 15 I/O6 (io) "Data Input/Output", 16 I/O7 (io) "Data Input/Output", 17 ~{WE} (in) "Write Enable Input", 18 A5 (in) "Address Input", 19 A6 (in) "Address Input", 20 A7 (in) "Address Input", 21 A8 (in) "Address Input", 22 A9 (in) "Address Input", 23 A10 (in) "Address Input", 24 A11 (in) "Address Input", 25 A12 (in) "Address Input", 26 A13 (in) "Address Input", 27 A14 (in) "Address Input", 28 NC "No Connection", 29 I/O8 (io) "Data Input/Output", 30 I/O9 (io) "Data Input/Output", 31 I/O10 (io) "Data Input/Output", 32 I/O11 (io) "Data Input/Output", 33 VDD (power) "Power", 34 GND (power) "Ground", 35 I/O12 (io) "Data Input/Output", 36 I/O13 (io) "Data Input/Output", 37 I/O14 (io) "Data Input/Output", 38 I/O15 (io) "Data Input/Output", 39 ~{LB} (in) "Lower-byte Control (I/O0-I/O7)", 40 ~{UB} (in) "Upper-byte Control (I/O8-I/O15)", 41 ~{OE} (in) "Output Enable Input", 42 A15 (in) "Address Input", 43 A16 (in) "Address Input", 44 A17 (in) "Address Input"

## IS61WV25616BLL-10TL
designator U?
4 M High Speed Asynchronous CMOS SRAM, 256 K x 16, 0 to 70 degC, 44-Pin SOP (TSOP-2-44), Pb-Free; Manufacturer: Integrated Silicon Solution Inc (ISSI); PartNumber: IS61WV25616BLL-10TL; Packing: Tray / Tube; Speed (ns): 10
footprint ISSI-TSOP-2-44_N (SOP, 44-Leads, Body 18.5x10.3mm, Pitch 0.8mm, IPC Medium Density)
pins: 1 A0 (in) "Address Input", 2 A1 (in) "Address Input", 3 A2 (in) "Address Input", 4 A3 (in) "Address Input", 5 A4 (in) "Address Input", 6 ~{CE} (in) "Chip Enable Input", 7 I/O0 (io) "Data Input/Output", 8 I/O1 (io) "Data Input/Output", 9 I/O2 (io) "Data Input/Output", 10 I/O3 (io) "Data Input/Output", 11 VDD (power) "Power", 12 GND (power) "Ground", 13 I/O4 (io) "Data Input/Output", 14 I/O5 (io) "Data Input/Output", 15 I/O6 (io) "Data Input/Output", 16 I/O7 (io) "Data Input/Output", 17 ~{WE} (in) "Write Enable Input", 18 A5 (in) "Address Input", 19 A6 (in) "Address Input", 20 A7 (in) "Address Input", 21 A8 (in) "Address Input", 22 A9 (in) "Address Input", 23 A10 (in) "Address Input", 24 A11 (in) "Address Input", 25 A12 (in) "Address Input", 26 A13 (in) "Address Input", 27 A14 (in) "Address Input", 28 NC "No Connection", 29 I/O8 (io) "Data Input/Output", 30 I/O9 (io) "Data Input/Output", 31 I/O10 (io) "Data Input/Output", 32 I/O11 (io) "Data Input/Output", 33 VDD (power) "Power", 34 GND (power) "Ground", 35 I/O12 (io) "Data Input/Output", 36 I/O13 (io) "Data Input/Output", 37 I/O14 (io) "Data Input/Output", 38 I/O15 (io) "Data Input/Output", 39 ~{LB} (in) "Lower-byte Control (I/O0-I/O7)", 40 ~{UB} (in) "Upper-byte Control (I/O8-I/O15)", 41 ~{OE} (in) "Output Enable Input", 42 A15 (in) "Address Input", 43 A16 (in) "Address Input", 44 A17 (in) "Address Input"

## IS61WV25616BLL-10TL-TR
designator U?
4 M High Speed Asynchronous CMOS SRAM, 256 K x 16, 0 to 70 degC, 44-Pin SOP (TSOP-2-44), Pb-Free; Manufacturer: Integrated Silicon Solution Inc (ISSI); PartNumber: IS61WV25616BLL-10TL-TR; Packing: Tape & Reel; Speed (ns): 10
footprint ISSI-TSOP-2-44_N (SOP, 44-Leads, Body 18.5x10.3mm, Pitch 0.8mm, IPC Medium Density)
pins: 1 A0 (in) "Address Input", 2 A1 (in) "Address Input", 3 A2 (in) "Address Input", 4 A3 (in) "Address Input", 5 A4 (in) "Address Input", 6 ~{CE} (in) "Chip Enable Input", 7 I/O0 (io) "Data Input/Output", 8 I/O1 (io) "Data Input/Output", 9 I/O2 (io) "Data Input/Output", 10 I/O3 (io) "Data Input/Output", 11 VDD (power) "Power", 12 GND (power) "Ground", 13 I/O4 (io) "Data Input/Output", 14 I/O5 (io) "Data Input/Output", 15 I/O6 (io) "Data Input/Output", 16 I/O7 (io) "Data Input/Output", 17 ~{WE} (in) "Write Enable Input", 18 A5 (in) "Address Input", 19 A6 (in) "Address Input", 20 A7 (in) "Address Input", 21 A8 (in) "Address Input", 22 A9 (in) "Address Input", 23 A10 (in) "Address Input", 24 A11 (in) "Address Input", 25 A12 (in) "Address Input", 26 A13 (in) "Address Input", 27 A14 (in) "Address Input", 28 NC "No Connection", 29 I/O8 (io) "Data Input/Output", 30 I/O9 (io) "Data Input/Output", 31 I/O10 (io) "Data Input/Output", 32 I/O11 (io) "Data Input/Output", 33 VDD (power) "Power", 34 GND (power) "Ground", 35 I/O12 (io) "Data Input/Output", 36 I/O13 (io) "Data Input/Output", 37 I/O14 (io) "Data Input/Output", 38 I/O15 (io) "Data Input/Output", 39 ~{LB} (in) "Lower-byte Control (I/O0-I/O7)", 40 ~{UB} (in) "Upper-byte Control (I/O8-I/O15)", 41 ~{OE} (in) "Output Enable Input", 42 A15 (in) "Address Input", 43 A16 (in) "Address Input", 44 A17 (in) "Address Input"

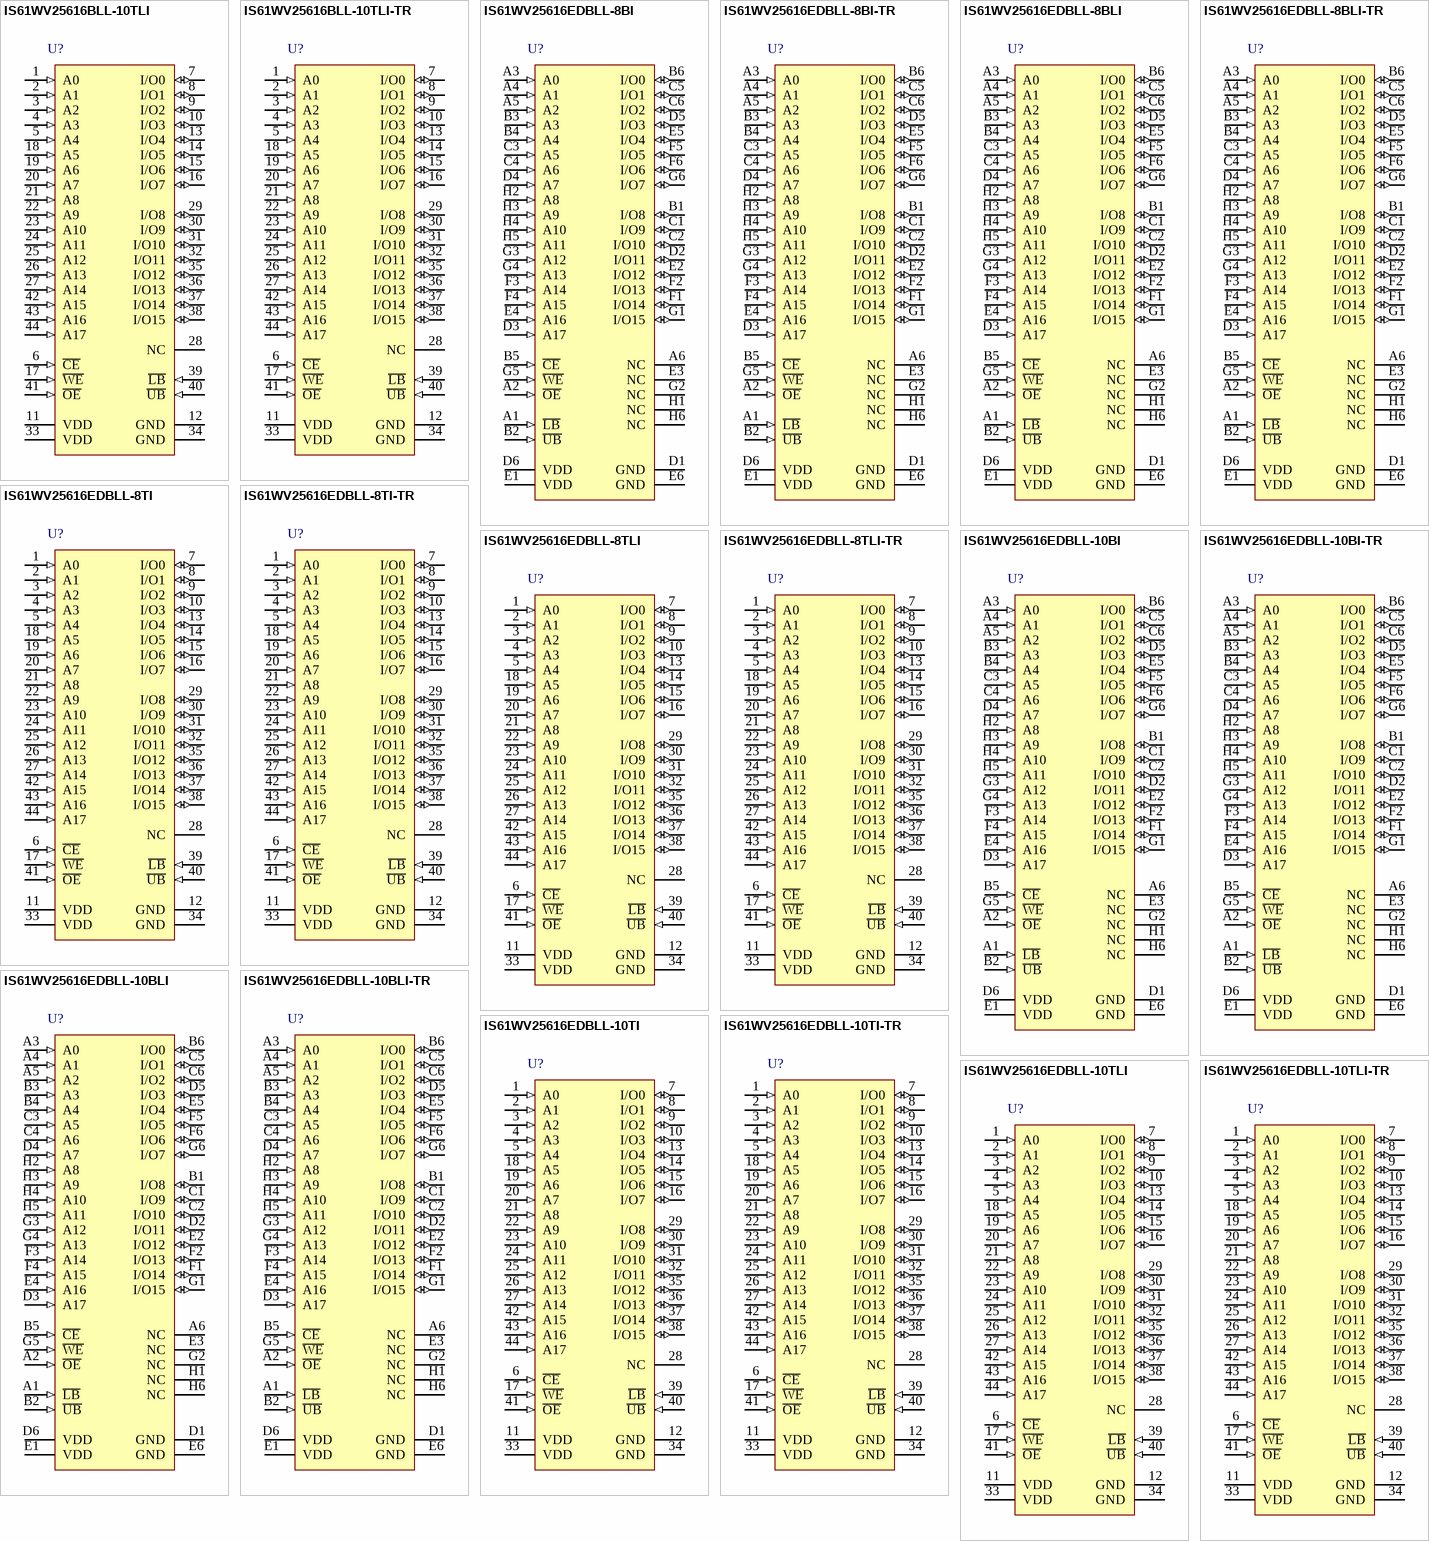
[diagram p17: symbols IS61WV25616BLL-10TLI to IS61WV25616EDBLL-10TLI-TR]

## IS61WV25616BLL-10TLI
designator U?
4 M High Speed Asynchronous CMOS SRAM, 256 K x 16, -40 to 85 degC, 44-Pin SOP (TSOP-2-44), Pb-Free; Manufacturer: Integrated Silicon Solution Inc (ISSI); PartNumber: IS61WV25616BLL-10TLI; Packing: Tray / Tube; Speed (ns): 10
footprint ISSI-TSOP-2-44_N (SOP, 44-Leads, Body 18.5x10.3mm, Pitch 0.8mm, IPC Medium Density)
pins: 1 A0 (in) "Address Input", 2 A1 (in) "Address Input", 3 A2 (in) "Address Input", 4 A3 (in) "Address Input", 5 A4 (in) "Address Input", 6 ~{CE} (in) "Chip Enable Input", 7 I/O0 (io) "Data Input/Output", 8 I/O1 (io) "Data Input/Output", 9 I/O2 (io) "Data Input/Output", 10 I/O3 (io) "Data Input/Output", 11 VDD (power) "Power", 12 GND (power) "Ground", 13 I/O4 (io) "Data Input/Output", 14 I/O5 (io) "Data Input/Output", 15 I/O6 (io) "Data Input/Output", 16 I/O7 (io) "Data Input/Output", 17 ~{WE} (in) "Write Enable Input", 18 A5 (in) "Address Input", 19 A6 (in) "Address Input", 20 A7 (in) "Address Input", 21 A8 (in) "Address Input", 22 A9 (in) "Address Input", 23 A10 (in) "Address Input", 24 A11 (in) "Address Input", 25 A12 (in) "Address Input", 26 A13 (in) "Address Input", 27 A14 (in) "Address Input", 28 NC "No Connection", 29 I/O8 (io) "Data Input/Output", 30 I/O9 (io) "Data Input/Output", 31 I/O10 (io) "Data Input/Output", 32 I/O11 (io) "Data Input/Output", 33 VDD (power) "Power", 34 GND (power) "Ground", 35 I/O12 (io) "Data Input/Output", 36 I/O13 (io) "Data Input/Output", 37 I/O14 (io) "Data Input/Output", 38 I/O15 (io) "Data Input/Output", 39 ~{LB} (in) "Lower-byte Control (I/O0-I/O7)", 40 ~{UB} (in) "Upper-byte Control (I/O8-I/O15)", 41 ~{OE} (in) "Output Enable Input", 42 A15 (in) "Address Input", 43 A16 (in) "Address Input", 44 A17 (in) "Address Input"

## IS61WV25616BLL-10TLI-TR
designator U?
4 M High Speed Asynchronous CMOS SRAM, 256 K x 16, -40 to 85 degC, 44-Pin SOP (TSOP-2-44), Pb-Free; Manufacturer: Integrated Silicon Solution Inc (ISSI); PartNumber: IS61WV25616BLL-10TLI-TR; Packing: Tape & Reel; Speed (ns): 10
footprint ISSI-TSOP-2-44_N (SOP, 44-Leads, Body 18.5x10.3mm, Pitch 0.8mm, IPC Medium Density)
pins: 1 A0 (in) "Address Input", 2 A1 (in) "Address Input", 3 A2 (in) "Address Input", 4 A3 (in) "Address Input", 5 A4 (in) "Address Input", 6 ~{CE} (in) "Chip Enable Input", 7 I/O0 (io) "Data Input/Output", 8 I/O1 (io) "Data Input/Output", 9 I/O2 (io) "Data Input/Output", 10 I/O3 (io) "Data Input/Output", 11 VDD (power) "Power", 12 GND (power) "Ground", 13 I/O4 (io) "Data Input/Output", 14 I/O5 (io) "Data Input/Output", 15 I/O6 (io) "Data Input/Output", 16 I/O7 (io) "Data Input/Output", 17 ~{WE} (in) "Write Enable Input", 18 A5 (in) "Address Input", 19 A6 (in) "Address Input", 20 A7 (in) "Address Input", 21 A8 (in) "Address Input", 22 A9 (in) "Address Input", 23 A10 (in) "Address Input", 24 A11 (in) "Address Input", 25 A12 (in) "Address Input", 26 A13 (in) "Address Input", 27 A14 (in) "Address Input", 28 NC "No Connection", 29 I/O8 (io) "Data Input/Output", 30 I/O9 (io) "Data Input/Output", 31 I/O10 (io) "Data Input/Output", 32 I/O11 (io) "Data Input/Output", 33 VDD (power) "Power", 34 GND (power) "Ground", 35 I/O12 (io) "Data Input/Output", 36 I/O13 (io) "Data Input/Output", 37 I/O14 (io) "Data Input/Output", 38 I/O15 (io) "Data Input/Output", 39 ~{LB} (in) "Lower-byte Control (I/O0-I/O7)", 40 ~{UB} (in) "Upper-byte Control (I/O8-I/O15)", 41 ~{OE} (in) "Output Enable Input", 42 A15 (in) "Address Input", 43 A16 (in) "Address Input", 44 A17 (in) "Address Input"

## IS61WV25616EDBLL-8BI
designator U?
4 M High Speed Asynchronous CMOS SRAM with ECC, 256 K x 16, -40 to 85 degC, 48-Pin BGA (TF-BGA-48); Manufacturer: Integrated Silicon Solution Inc (ISSI); PartNumber: IS61WV25616EDBLL-8BI; Density: 4M; Packing: Tray / Tube; Speed (ns): 8
footprint ISSI-TF-BGA-48-6000X8000DE (BGA, 48-Balls, Body 8x6mm, Pitch 0.75mm)
pins: A1 ~{LB} (in) "Lower-byte Control (I/O0-I/O7)", A2 ~{OE} (in) "Output Enable Input", A3 A0 (in) "Address Input", A4 A1 (in) "Address Input", A5 A2 (in) "Address Input", A6 NC "No Connection", B1 I/O8 (io) "Data Input/Output", B2 ~{UB} (in) "Upper-byte Control (I/O8-I/O15)", B3 A3 (in) "Address Input", B4 A4 (in) "Address Input", B5 ~{CE} (in) "Chip Enable Input", B6 I/O0 (io) "Data Input/Output", C1 I/O9 (io) "Data Input/Output", C2 I/O10 (io) "Data Input/Output", C3 A5 (in) "Address Input", C4 A6 (in) "Address Input", C5 I/O1 (io) "Data Input/Output", C6 I/O2 (io) "Data Input/Output", D1 GND (power) "Ground", D2 I/O11 (io) "Data Input/Output", D3 A17 (in) "Address Input", D4 A7 (in) "Address Input", D5 I/O3 (io) "Data Input/Output", D6 VDD (power) "Power", E1 VDD (power) "Power", E2 I/O12 (io) "Data Input/Output", E3 NC "No Connection", E4 A16 (in) "Address Input", E5 I/O4 (io) "Data Input/Output", E6 GND (power) "Ground", F1 I/O14 (io) "Data Input/Output", F2 I/O13 (io) "Data Input/Output", F3 A14 (in) "Address Input", F4 A15 (in) "Address Input", F5 I/O5 (io) "Data Input/Output", F6 I/O6 (io) "Data Input/Output", G1 I/O15 (io) "Data Input/Output", G2 NC "No Connection", G3 A12 (in) "Address Input", G4 A13 (in) "Address Input", G5 ~{WE} (in) "Write Enable Input", G6 I/O7 (io) "Data Input/Output", H1 NC "No Connection", H2 A8 (in) "Address Input", H3 A9 (in) "Address Input", H4 A10 (in) "Address Input", H5 A11 (in) "Address Input", H6 NC "No Connection"

## IS61WV25616EDBLL-8BI-TR
designator U?
4 M High Speed Asynchronous CMOS SRAM with ECC, 256 K x 16, -40 to 85 degC, 48-Pin BGA (TF-BGA-48); Manufacturer: Integrated Silicon Solution Inc (ISSI); PartNumber: IS61WV25616EDBLL-8BI-TR; Density: 4M; Packing: Tape & Reel; Speed (ns): 8
footprint ISSI-TF-BGA-48-6000X8000DE (BGA, 48-Balls, Body 8x6mm, Pitch 0.75mm)
pins: A1 ~{LB} (in) "Lower-byte Control (I/O0-I/O7)", A2 ~{OE} (in) "Output Enable Input", A3 A0 (in) "Address Input", A4 A1 (in) "Address Input", A5 A2 (in) "Address Input", A6 NC "No Connection", B1 I/O8 (io) "Data Input/Output", B2 ~{UB} (in) "Upper-byte Control (I/O8-I/O15)", B3 A3 (in) "Address Input", B4 A4 (in) "Address Input", B5 ~{CE} (in) "Chip Enable Input", B6 I/O0 (io) "Data Input/Output", C1 I/O9 (io) "Data Input/Output", C2 I/O10 (io) "Data Input/Output", C3 A5 (in) "Address Input", C4 A6 (in) "Address Input", C5 I/O1 (io) "Data Input/Output", C6 I/O2 (io) "Data Input/Output", D1 GND (power) "Ground", D2 I/O11 (io) "Data Input/Output", D3 A17 (in) "Address Input", D4 A7 (in) "Address Input", D5 I/O3 (io) "Data Input/Output", D6 VDD (power) "Power", E1 VDD (power) "Power", E2 I/O12 (io) "Data Input/Output", E3 NC "No Connection", E4 A16 (in) "Address Input", E5 I/O4 (io) "Data Input/Output", E6 GND (power) "Ground", F1 I/O14 (io) "Data Input/Output", F2 I/O13 (io) "Data Input/Output", F3 A14 (in) "Address Input", F4 A15 (in) "Address Input", F5 I/O5 (io) "Data Input/Output", F6 I/O6 (io) "Data Input/Output", G1 I/O15 (io) "Data Input/Output", G2 NC "No Connection", G3 A12 (in) "Address Input", G4 A13 (in) "Address Input", G5 ~{WE} (in) "Write Enable Input", G6 I/O7 (io) "Data Input/Output", H1 NC "No Connection", H2 A8 (in) "Address Input", H3 A9 (in) "Address Input", H4 A10 (in) "Address Input", H5 A11 (in) "Address Input", H6 NC "No Connection"

## IS61WV25616EDBLL-8BLI
designator U?
4 M High Speed Asynchronous CMOS SRAM with ECC, 256 K x 16, -40 to 85 degC, 48-Pin BGA (TF-BGA-48), Pb-Free; Manufacturer: Integrated Silicon Solution Inc (ISSI); PartNumber: IS61WV25616EDBLL-8BLI; Density: 4M; Packing: Tray / Tube; Speed (ns): 8
footprint ISSI-TF-BGA-48-6000X8000DE (BGA, 48-Balls, Body 8x6mm, Pitch 0.75mm)
pins: A1 ~{LB} (in) "Lower-byte Control (I/O0-I/O7)", A2 ~{OE} (in) "Output Enable Input", A3 A0 (in) "Address Input", A4 A1 (in) "Address Input", A5 A2 (in) "Address Input", A6 NC "No Connection", B1 I/O8 (io) "Data Input/Output", B2 ~{UB} (in) "Upper-byte Control (I/O8-I/O15)", B3 A3 (in) "Address Input", B4 A4 (in) "Address Input", B5 ~{CE} (in) "Chip Enable Input", B6 I/O0 (io) "Data Input/Output", C1 I/O9 (io) "Data Input/Output", C2 I/O10 (io) "Data Input/Output", C3 A5 (in) "Address Input", C4 A6 (in) "Address Input", C5 I/O1 (io) "Data Input/Output", C6 I/O2 (io) "Data Input/Output", D1 GND (power) "Ground", D2 I/O11 (io) "Data Input/Output", D3 A17 (in) "Address Input", D4 A7 (in) "Address Input", D5 I/O3 (io) "Data Input/Output", D6 VDD (power) "Power", E1 VDD (power) "Power", E2 I/O12 (io) "Data Input/Output", E3 NC "No Connection", E4 A16 (in) "Address Input", E5 I/O4 (io) "Data Input/Output", E6 GND (power) "Ground", F1 I/O14 (io) "Data Input/Output", F2 I/O13 (io) "Data Input/Output", F3 A14 (in) "Address Input", F4 A15 (in) "Address Input", F5 I/O5 (io) "Data Input/Output", F6 I/O6 (io) "Data Input/Output", G1 I/O15 (io) "Data Input/Output", G2 NC "No Connection", G3 A12 (in) "Address Input", G4 A13 (in) "Address Input", G5 ~{WE} (in) "Write Enable Input", G6 I/O7 (io) "Data Input/Output", H1 NC "No Connection", H2 A8 (in) "Address Input", H3 A9 (in) "Address Input", H4 A10 (in) "Address Input", H5 A11 (in) "Address Input", H6 NC "No Connection"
